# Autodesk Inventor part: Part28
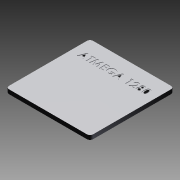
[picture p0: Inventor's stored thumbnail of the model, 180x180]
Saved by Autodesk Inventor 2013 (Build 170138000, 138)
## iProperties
Created: 2012-07
Part Number: Part28
Material: Generic
Document SubType Name: Modeling
Designer: Paul
Density: 1 g/cm^3
Author: Paul
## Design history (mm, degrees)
node "User Library-Arduino Mega.SAT1"
body "Solid1"
node "Base1"
